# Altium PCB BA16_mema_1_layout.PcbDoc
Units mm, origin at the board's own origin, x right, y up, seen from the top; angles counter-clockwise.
Board outline 42 x 70 mm, 2 copper layers (Top Layer, Bottom Layer); 44 components, 23 nets, 138 pads, 166 vias.
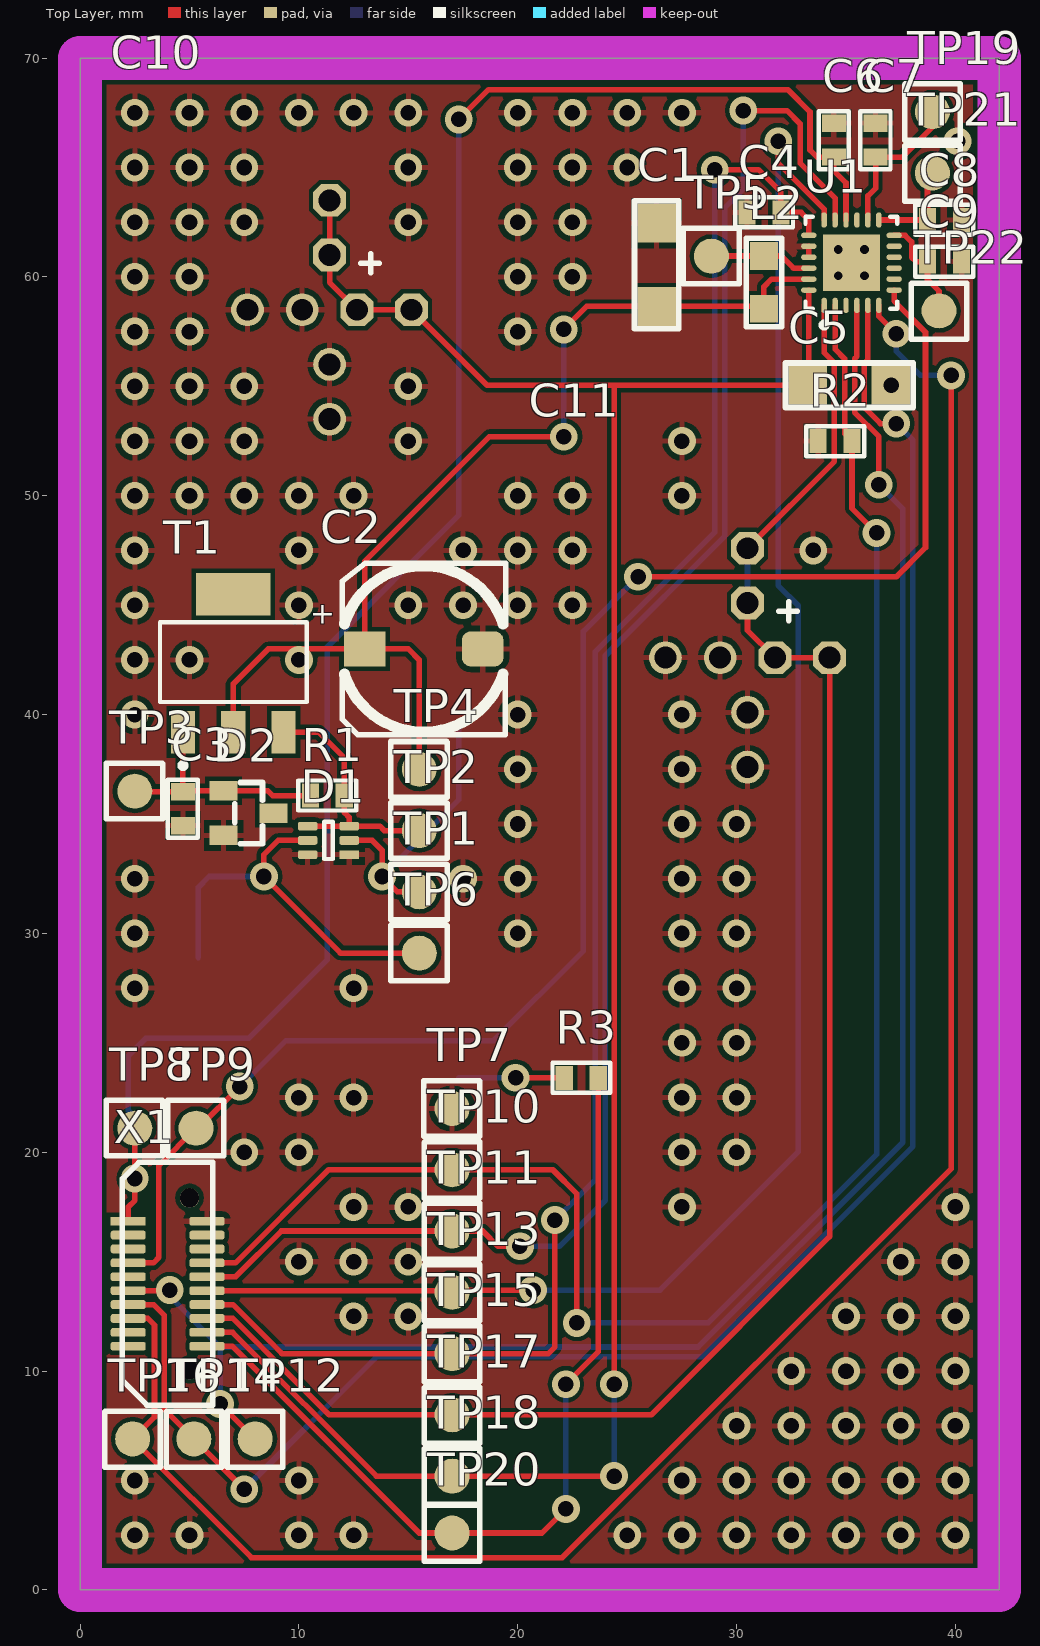
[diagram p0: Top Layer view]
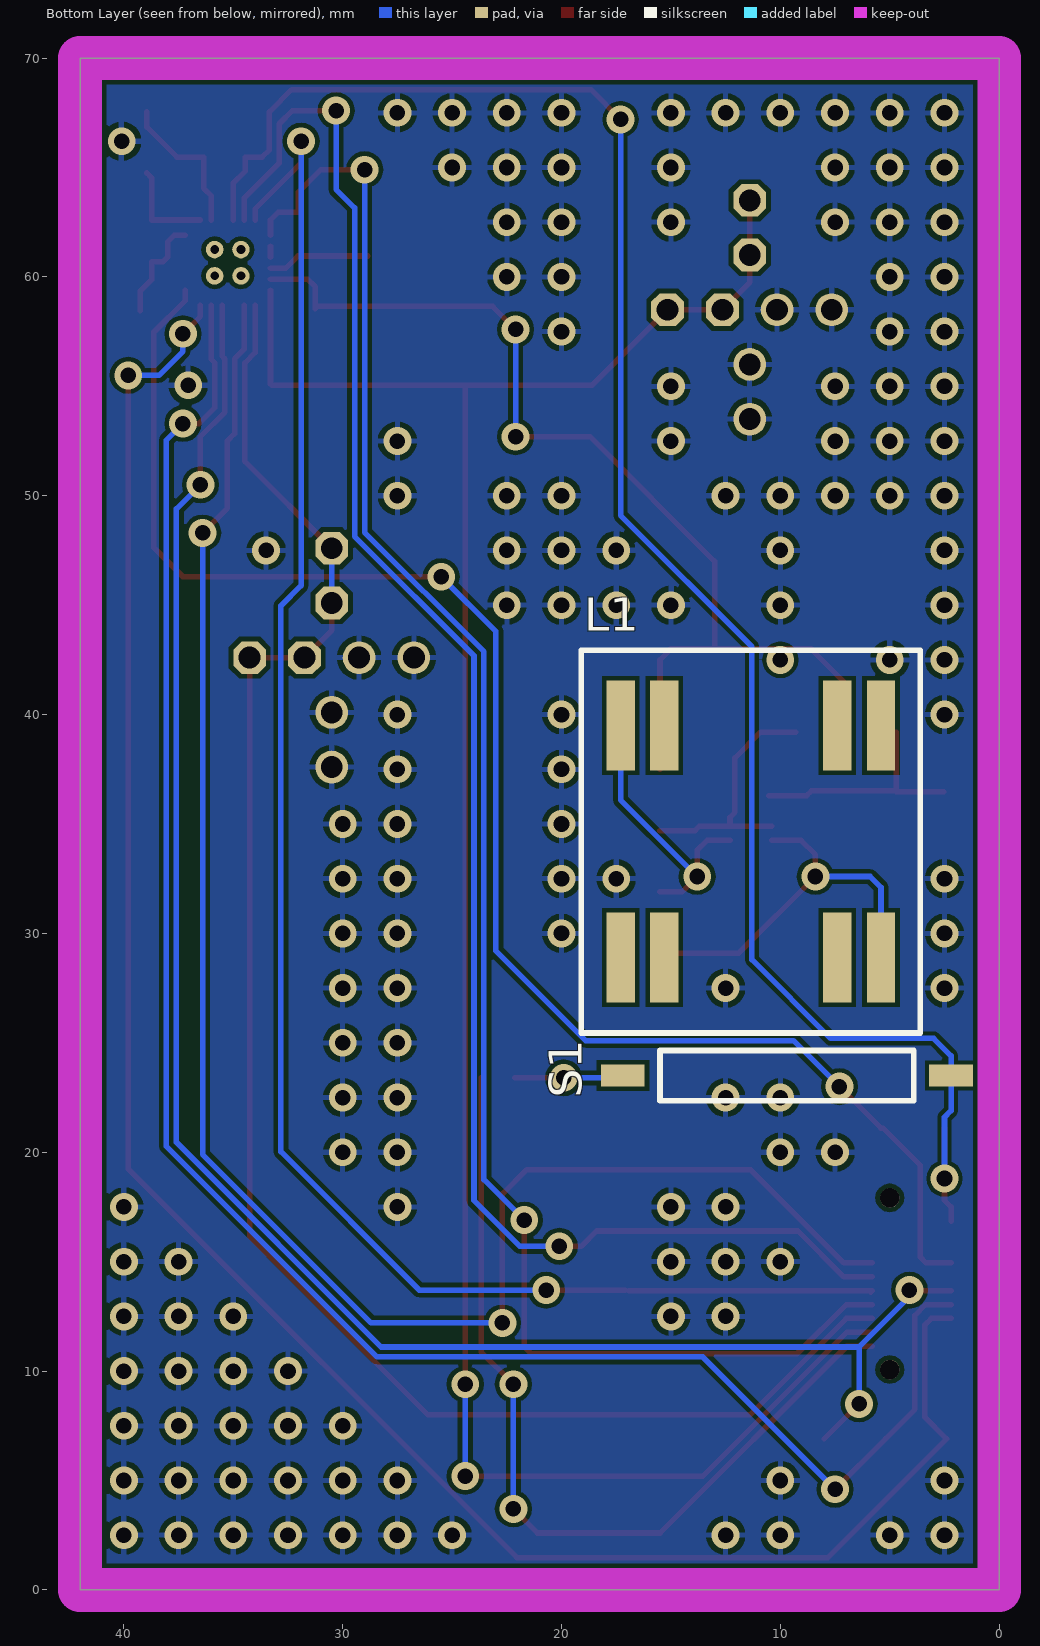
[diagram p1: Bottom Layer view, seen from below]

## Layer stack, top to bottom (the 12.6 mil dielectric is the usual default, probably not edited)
Top Solder: solder mask 0.0102, Solder Resist, Dk 3.5
Top Layer: signal copper 0.0356
Dielectric 1: dielectric 0.32, FR-4, Dk 4.8
Bottom Layer: signal copper 0.0356
Bottom Solder: solder mask 0.0102, Solder Resist, Dk 3.5

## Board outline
0,0 0,70 42,70 42,0

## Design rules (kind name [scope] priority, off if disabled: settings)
Clearance Clearance_EM8500 [All] p1: gap=0.2
Clearance [All] p2: gap=0.254
ComponentClearance ComponentClearance_ELKO_FLEX [HasFootprint('C_RAD_flex')] p1: gap=-5 collisioncheckmode=3 verticalgap=0.254 showdistances=FALSE
ComponentClearance ComponentClearance_TP [HasFootprint('TP SMD')] p2: gap=0 collisioncheckmode=3 verticalgap=0 showdistances=FALSE
ComponentClearance [All] p3: gap=0.254 collisioncheckmode=3 verticalgap=0.254 showdistances=FALSE
PolygonConnect [All] p1: connectstyle=Relief reliefconductorwidth=0.254 reliefentries=4 polygonreliefangle="90 Angle" airgapwidth=0.254
RoutingVias [All] p1: holewidth=0.711 width=1.27 viastyle="Through Hole" minholewidth=0.711 minwidth=1.27 maxholewidth=0.711 maxwidth=1.27
SilkToSilkClearance SilkToSilkClearance_TP [HasFootprint('TP SMD')] p1: silktosilkclearance=0
SilkToSilkClearance [All] p2: silktosilkclearance=0.254
SolderMaskExpansion [All] p1: expansion=0.102
Width [All] p1: maxlimit=0.254 minlimit=0.254 preferedwidth=0.254
28 further rules are at their usual default settings.

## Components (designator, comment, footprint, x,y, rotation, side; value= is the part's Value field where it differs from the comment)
C1 "Cap" "CHIP 1206" 26.35,58.65 r90 top
C2 "47uF 25V" "ELKO SMD-C 6.3x6.3" 15.7,43 r0 top
C3 "1nF" "CHIP 0603" 4.7,35.7 r90 top
C4 "Cap" "CHIP 0603" 31.25,62.95 r180 top
C5 "Cap" "CHIP 1206" 33.25,55.05 r0 top
C6 "Cap" "CHIP 0603" 34.45,66.25 r90 top
C7 "Cap" "CHIP 0603" 36.35,66.25 r90 top
C8 "Cap" "CHIP 0603" 39.5,62.6 r0 top
C9 "Cap" "CHIP 0603" 39.5,60.7 r0 top
C10 "3300uF 25V" C_RAD_FLEX 11.4,58.5 r0 top
C11 "470uF 25V" C_RAD_FLEX 30.5,42.6 r0 top
D1 "HSMS-286P" "SOT-363 (SC-70)" 12.3,33.6 r180 top
D2 "BAS16" SOT-23 7.7,35.5 r270 top
L1 "X-Wicklung" PREMO_3115N_0238J_2 17.3,28.9 r90 bottom
L2 "L" "CHIP 0805" 31.25,59.75 r270 top
R1 "1M" "CHIP 0603" 11.3,36.3 r0 top
R2 "R" "CHIP 0603" 34.5,52.5 r180 top
R3 "10k 0603" "CHIP 0603" 22.9,23.4 r180 top
S1 "Reed Switch" MK16-C-2 9.7,23.5 r180 bottom
T1 "BSP149" SOT-223 4.7,39.2 r0 top
TP1 "TP_SMD" "TP SMD" 15.5,31.9 r0 top
TP2 "TP_SMD" "TP SMD" 15.5,34.7 r0 top
TP3 "TP_SMD" "TP SMD" 2.5,36.5 r0 top
TP4 "TP_SMD" "TP SMD" 15.5,37.5 r0 top
TP5 "TP_SMD" "TP SMD" 28.85,60.95 r0 top
TP6 "TP_SMD" "TP SMD" 15.5,29.1 r0 top
TP7 "TP_SMD" "TP SMD" 17,22 r0 top
TP8 "TP_SMD" "TP SMD" 2.5,21.1 r0 top
TP9 "TP_SMD" "TP SMD" 5.3,21.1 r0 top
TP10 "TP_SMD" "TP SMD" 17,19.2 r90 top
TP11 "TP_SMD" "TP SMD" 17,16.4 r90 top
TP12 "TP_SMD" "TP SMD" 8,6.9 r90 top
TP13 "TP_SMD" "TP SMD" 17,13.6 r90 top
TP14 "TP_SMD" "TP SMD" 5.2,6.9 r90 top
TP15 "TP_SMD" "TP SMD" 17,10.8 r90 top
TP16 "TP_SMD" "TP SMD" 2.4,6.9 r90 top
TP17 "TP_SMD" "TP SMD" 17,8 r90 top
TP18 "TP_SMD" "TP SMD" 17,5.2 r90 top
TP19 "TP_SMD" "TP SMD" 38.95,67.55 r90 top
TP20 "TP_SMD" "TP SMD" 17,2.6 r90 top
TP21 "TP_SMD" "TP SMD" 38.95,64.75 r90 top
TP22 "TP_SMD" "TP SMD" 39.25,58.45 r90 top
U1 "em8500" QFN-24 35.25,60.65 r90 top
X1 "LSS-110-01-F-DV-A-TR" "HEADER SMD 2X10 0.635MM" 2.2,16.85 r0 top locked

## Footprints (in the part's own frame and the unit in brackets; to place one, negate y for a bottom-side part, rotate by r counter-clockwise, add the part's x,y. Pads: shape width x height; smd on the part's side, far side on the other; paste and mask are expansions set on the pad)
C_RAD_FLEX [mm] "KONDENSATOR, AXIAL, Raster 5"
  oct 1.5x1.5 hole 1: 1(0,2.5) 1(0,5) 1(1.25,0) 1(3.75,0)
  round 1.5 hole 1: 2(-3.75,0) 2(-1.25,0) 2(0,-5) 2(0,-2.5)
  silkscreen extent 1.42,1.7 2.27,2.55
"CHIP 0603" [mil] "Chip 0603 Body 1.6x0.8mm"
  rect 31x43 smd: 1(-30.5,0) 2(30.5,0)
  silkscreen extent -52,-27 52,27
"CHIP 0805" [mil] "Chip 0805 Body 2.0x1.2mm"
  rect 50x50 smd: 1(-47.5,0) 2(47.5,0)
  silkscreen extent -80,-32 80,32
"CHIP 1206" [mil] "Chip 1206 Body 3.2x1.6mm"
  rect 70x70 smd: 1(0,0) 2(150,0)
  silkscreen extent -40,-40 190,40
"ELKO SMD-C 6.3x6.3" [mm] "Elko SMD Size C 6.3x6.3mm H = 5.5mm"
  rect 1.9x1.6 smd: 1(-2.7,0)
  rrect50% 1.9x1.6 smd: 2(2.7,0)
  silkscreen extent -3.72,-3.93 3.75,3.93
"HEADER SMD 2X10 0.635MM" [mm] "LSS-110-01-F-DV-A"
  round 0.89 hole 0.89 unplated: 0(2.8,-6.783) 0(2.8,1.068)
  rect 1.6x0.4 smd: 1(0,0)
  rrect50% 1.6x0.4 smd: 2(3.6,0) 3(0,-0.635) 4(3.6,-0.635) 5(0,-1.27) 6(3.6,-1.27) 7(0,-1.905) 8(3.6,-1.905) 9(0,-2.54) 10(3.6,-2.54) 11(0,-3.175) 12(3.6,-3.175) 13(0,-3.81) 14(3.6,-3.81) 15(0,-4.445) 16(3.6,-4.445) 17(0,-5.08) 18(3.6,-5.08) 19(0,-5.715) 20(3.6,-5.715)
  silkscreen extent -0.27,-8.4 3.87,2.69
MK16-C-2 [mm] "REED SENSOR"
  rect 2x1 smd: 1(-7.5,0) 2(7.5,0)
  silkscreen extent -5.8,-1.15 5.8,1.15
PREMO_3115N_0238J_2 [mm] "3D Coil 15x15 2.38mH +/-5% @125kHz"
  rect 4.1x1.3 smd: 1(0,0) 2(0,-2) 3(0,-9.9) 4(0,-11.9) 5(10.6,-11.9) 6(10.6,-9.9) 7(10.6,-2) 8(10.6,0)
  silkscreen extent -3.45,-13.7 14.05,1.8
QFN-24 [mm] "24-Pin Plastic Quad Flat No-Lead 0.5 mm Pitch"
  oval 0.7x0.25 smd: 1(-1.95,1.25) 2(-1.95,0.75) 3(-1.95,0.25) 4(-1.95,-0.25) 5(-1.95,-0.75) 6(-1.95,-1.25) 13(1.95,-1.25) 14(1.95,-0.75) 15(1.95,-0.25) 16(1.95,0.25) 17(1.95,0.75) 18(1.95,1.25)
  oval 0.25x0.7 smd: 7(-1.25,-1.95) 8(-0.75,-1.95) 9(-0.25,-1.95) 10(0.25,-1.95) 11(0.75,-1.95) 12(1.25,-1.95) 19(1.25,1.95) 20(0.75,1.95) 21(0.25,1.95) 22(-0.25,1.95) 23(-0.75,1.95) 24(-1.25,1.95)
  round 0.8 hole 0.4: 25(-0.6,-0.6) 25(-0.6,0.6) 25(0.6,-0.6) 25(0.6,0.6)
  rect 2.6x2.6 smd: 25(0,0)
  silkscreen extent -2.97,-2.1 2.1,2.1, body extent -2.07,-2.07 2.07,2.07, height 1
SOT-23 [mil]
  rect 35x50 smd: 1(-40,-45) 2(40,-45) 3(0,45)
  silkscreen extent -55,-25 55,25
SOT-223 [mm] "SOT-223/SC-73; 4 Leads; Body 6.7 x 7.3 mm, inc. leads (LxW max)"
  rect 1.1x1.95 smd: 1(0,0) 2(2.3,0) 3(4.6,0)
  rect 3.4x1.95 smd: 4(2.3,6.3)
  silkscreen extent -1.05,-1.65 5.65,5.02
"SOT-363 (SC-70)" [mm]
  rect 0.9x0.4 smd: 1(0,0)
  rrect50% 0.9x0.4 smd: 2(0,-0.65) 3(0,-1.3) 4(1.9,-1.3) 5(1.9,-0.65) 6(1.9,0)
  silkscreen extent 0.75,-1.5 1.15,0.2
"TP SMD" [mm] "Testpoint SMD"
  round 1.6 smd: 1(0,0)
  silkscreen extent -1.3,-1.27 1.27,1.27

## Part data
C1 C4 C5 C6 C7 C8 C9: library part C, "Capacitor"
C2 C10 C11: library part "C POL", "Capasitor Polarisiert"
C3: library part "C 50V", "Capacitor 50V"
D1: "Diode Schottky Quadro"
D2: library part D, "Diode"
L1: library part "PREMO 3015 0238J 2", "Inductor"
L2: "Ind"
R1 R3: library part R, "Resistor"
R2: "Resistor"
S1: library part "SWITCH MICRO NO", "Switch Micro Normal Open"
T1: "MOSFET N-Kanal"
TP1 TP2 TP3 TP4 TP5 TP6 TP7 TP8 TP9 TP10 TP11 TP12 TP13 TP14 TP15 TP16 TP17 TP18 TP19 TP20 TP21 TP22: "Testpoint SMD"
X1: library part "HDR 20 POL ABW", "Header 100 mil 20 Pol"

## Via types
v1: diameter 1.27, hole 0.711, Top Layer to Bottom Layer, 166 vias

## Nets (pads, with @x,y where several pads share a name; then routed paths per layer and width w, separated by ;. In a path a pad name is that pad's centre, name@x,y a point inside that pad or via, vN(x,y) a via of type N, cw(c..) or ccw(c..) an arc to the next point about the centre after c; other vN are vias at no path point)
BAT_LOW: TP13.1 U1.18 X1.12 | length 80.6
  Top Layer w0.254: X1.12@5.875,13.6 X1.12 TP13.1@16.925,13.675 ; TP13.1@17.1,13.7 v1(20.7,13.7) ; v1(31.9,66.2) 31.9,65.2 34,63.1 U1.18
  Bottom Layer w0.254: v1(20.7,13.7) 26.5,13.7 32.827,20.027 32.827,44.973 31.9,45.9 v1(31.9,66.2)
EM_CS: TP9.1 U1.7 X1.7 | length 73.2
  Top Layer w0.254: X1.7 3.345,14.945 3.6,15.2 3.6,19.4 TP9.1 ; TP9.1@5.4,21.1 v1(7.3,23) ; v1(25.5,46.3) 37.3,46.3 38.633,47.633 38.633,57.473 37.2,58.906 U1.7
  Bottom Layer w0.254: v1(7.3,23) 9.4,25.1 18.9,25.1 23,29.2 23,43.8 v1(25.5,46.3)
GND: C1.2 C2.2 C3.1 C4.2 C5.2 C6.2 C7.2 C8.2 C9.2 C10.2 C11.2 D1.1 D1.6 D2.2 R2.2 TP7.1 U1.20 U1.21 X1.2 | length 0.5
  Top Layer w0.254: U1.21 U1.20
  other v1: 2.5,2.5 5,2.5 10,2.5 12.5,2.5 25,2.5 27.5,2.5 30,2.5 32.5,2.5 35,2.5 37.5,2.5 40,2.5 2.5,5 10,5 27.5,5 30,5 32.5,5 35,5 37.5,5 40,5 30,7.5 32.5,7.5 35,7.5 35,7.5 37.5,7.5 40,7.5 32.5,10 35,10 37.5,10 40,10 12.5,12.5 15,12.5 35,12.5 37.5,12.5 40,12.5 10,15 12.5,15 15,15 37.5,15 40,15 12.5,17.5 15,17.5 27.5,17.5 40,17.5 7.5,20 10,20 27.5,20 30,20 10,22.5 12.5,22.5 27.5,22.5 30,22.5 27.5,25 30,25 2.5,27.5 12.5,27.5 27.5,27.5 30,27.5 2.5,30 20,30 27.5,30 30,30 2.5,32.5 17.5,32.5 20,32.5 27.5,32.5 30,32.5 20,35 27.5,35 30,35 20,37.5 27.5,37.5 2.5,40 20,40 27.5,40 2.5,42.5 5,42.5 2.5,45 10,45 15,45 17.5,45 20,45 22.5,45 2.5,47.5 10,47.5 17.5,47.5 20,47.5 22.5,47.5 33.5,47.5 2.5,50 5,50 7.5,50 10,50 12.5,50 20,50 22.5,50 27.5,50 2.5,52.5 5,52.5 7.5,52.5 15,52.5 27.5,52.5 2.5,55 5,55 7.5,55 15,55 37.06,55.05 2.5,57.5 5,57.5 20,57.5 2.5,60 5,60 20,60 22.5,60 2.5,62.5 5,62.5 7.5,62.5 15,62.5 20,62.5 22.5,62.5 2.5,65 5,65 7.5,65 15,65 20,65 22.5,65 25,65 40.1,66.2 2.5,67.5 5,67.5 7.5,67.5 10,67.5 12.5,67.5 15,67.5 20,67.5 22.5,67.5 25,67.5 27.5,67.5
HRV_LOW: TP11.1 U1.17 X1.10 | length 80.5
  Top Layer w0.254: X1.10 7.11,14.31 9.2,16.4 TP11.1 18.4,16.4 19.1,15.7 v1(20.1,15.7) ; v1(30.3,67.6) 32.3,67.6 32.9,67 32.9,65.2 34.5,63.6 U1.17
  Bottom Layer w0.254: v1(20.1,15.7) 21.9,15.7 24,17.8 24,42.687 29.454,48.141 29.454,63.154 30.3,64 v1(30.3,67.6)
MCU_MISO: TP14.1 U1.5 X1.13 | length 88.2
  Top Layer w0.254: X1.13 3.36,13.04 3.854,12.546 3.854,8.246 TP14.1 v1(7.5,4.6) ; U1.5 36,56.23 35.844,56.074 35.844,54.026 36.57,53.3 v1(37.3,53.3)
  Bottom Layer w0.254: v1(7.5,4.6) 13.546,10.646 28.43,10.646 38.054,20.27 38.054,52.546 v1(37.3,53.3)
MCU_MOSI: TP12.1 U1.4 X1.11 | length 87.2
  Top Layer w0.254: X1.11 4.075,13.675 v1(4.1,13.7) ; v1(6.4,8.5) TP12.1 ; U1.4 35.5,56.372 35.39,56.262 35.39,53.81 36.5,52.7 v1(36.5,50.5)
  Bottom Layer w0.254: v1(4.1,13.7) 4.1,13.4 6.4,11.1 ; v1(36.5,50.5) 37.6,49.4 37.6,20.458 28.242,11.1 6.4,11.1 ; 6.4,11.1 v1(6.4,8.5) 6.4,11.1
MCU_SCLK: TP16.1 U1.6 X1.15 | length 95.6
  Top Layer w0.254: X1.15 3.095,12.405 3.4,12.1 3.4,7.9 TP16.1 7.827,1.473 22.033,1.473 39.8,19.24 v1(39.8,55.5) ; U1.6 36.5,58.2 v1(37.3,57.4)
  Bottom Layer w0.254: v1(37.3,57.4) 37.3,56.6 38.4,55.5 v1(39.8,55.5)
NetC3_2: C3.2 D2.1 R1.1 T1.1 TP3.1 | length 10.8
  Top Layer w0.254: TP3.1@2.525,36.475 C3.2 T1.1 ; C3.2@4.741,36.516 D2.1 8.584,36.516 8.8,36.3 R1.1
NetD1_2: D1.2 L1.8 TP1.1 | length 13.2
  Top Layer w0.254: D1.2 13.35,34.25 13.8,33.8 v1(13.8,32.6) 14.5,31.9 TP1.1
  Bottom Layer w0.254: v1(13.8,32.6) 17.3,36.1 L1.8
NetD1_3: D1.3 D1.4 R1.2 T1.3 TP2.1 | length 11.7
  Top Layer w0.254: T1.3 10.9,39.2 12.075,38.025 R1.2 12.075,35.525 12.3,35.3 D1.3 ; D1.4 D1.3 ; TP2.1 13.9,34.7 13.7,34.9 D1.3
NetD1_5: D1.5 L1.4 TP6.1 | length 18.2
  Top Layer w0.254: D1.5 9.05,34.25 8.4,33.6 v1(8.4,32.6) 11.9,29.1 TP6.1
  Bottom Layer w0.254: L1.4 5.4,32.1 5.9,32.6 v1(8.4,32.6)
NetL2_1: L2.1 TP5.1 U1.22 | length 4.7
  Top Layer w0.254: TP5.1@28.857,60.956 L2.1 32.044,60.956 32.6,60.4 U1.22
NetR3_2: R3.2 S1.1 | length 4.8
  Top Layer w0.254: v1(19.9,23.4) R3.2
  Bottom Layer w0.254: S1.1@17.3,23.4 v1(19.9,23.4)
REED_SWITCH: R3.1 TP20.1 X1.20 | length 40.7
  Top Layer w0.254: X1.20 6.965,11.135 15.5,2.6 21.1,2.6 v1(22.2,3.7) ; v1(22.2,9.4) 23.675,10.875 R3.1
  Bottom Layer w0.254: v1(22.2,3.7) v1(22.2,9.4)
VAUX_VCC0: C9.1 TP22.1 U1.12 | length 4.9
  Top Layer w0.254: U1.12 37.7,61.9 38,61.6 38,60.9 38.2,60.7 C9.1 38.725,59.875 39.25,59.35 TP22.1
VAUX_VCC1: C8.1 TP21.1 U1.13 | length 4.5
  Top Layer w0.254: U1.13 C8.1 38.725,64.525 TP21.1
VAUX_VCC2: C7.1 TP19.1 U1.14 | length 6.9
  Top Layer w0.254: U1.14 36,63.7 36.35,64.05 C7.1 37.575,65.475 38.95,66.85 TP19.1
VCC: C1.1 C2.1 L2.2 T1.2 TP4.1 U1.23 | length 49.6
  Top Layer w0.254: T1.2 7,41.4 8.6,43 C2.1 ; TP4.1 15.5,42.5 15,43 C2.1 ; v1(22.1,52.7) 18.7,52.7 13,47 C2.1 ; v1(22.1,57.6) 23.15,58.65 C1.1 L2.2@31.144,58.65 ; L2.2 31.25,59.55 31.6,59.9 U1.23
  Bottom Layer w0.254: v1(22.1,52.7) v1(22.1,57.6)
  other v1: 10,42.5
VCC_LTS: C5.1 C10.1 TP18.1 U1.24 X1.18 | length 103
  Top Layer w0.254: X1.18 6.972,11.77 13.542,5.2 TP18.1 v1(24.4,5.2) ; C10.1@11.4,63.5 11.4,61 11.4,59.75 12.65,58.5 15.15,58.5 18.6,55.05 24.4,55.05 ; v1(24.4,9.4) 24.4,55.05 ; C5.1 24.4,55.05 ; C5.1@33.3,55.1 U1.24
  Bottom Layer w0.254: v1(24.4,5.2) v1(24.4,9.4)
VCC_STS: C11.1 TP17.1 U1.1 X1.16 | length 81.1
  Top Layer w0.254: X1.16 6.979,12.405 11.384,8 TP17.1 26.1,8 34.25,16.15 34.25,42.6 31.75,42.6 30.5,43.85 C11.1@30.5,45.1 ; C11.1@30.5,47.6 34.466,51.566 34.466,56.074 34,56.54 U1.1
  Bottom Layer w0.254: C11.1@30.5,45.1 C11.1@30.5,47.6
VREG: C4.1 TP15.1 U1.19 X1.14 | length 80.3
  Top Layer w0.254: X1.14 6.986,13.04 9.226,10.8 TP15.1 21.4,10.8 21.7,11.1 v1(21.7,16.9) ; v1(29,64.9) 31,64.9 32.025,63.875 C4.1 32.95,62.95 33.3,62.6 U1.19
  Bottom Layer w0.254: v1(21.7,16.9) 23.546,18.746 23.546,42.875 29,48.329 v1(29,64.9)
VSUP: C6.1 S1.2 TP8.1 U1.16 X1.1 | length 85
  Top Layer w0.254: X1.1 2.2,17.5 2.5,17.8 v1(2.5,18.8) TP8.1 ; v1(17.3,67.2) 18.662,68.562 32.338,68.562 33.354,67.546 33.354,65.8 33.679,65.475 C6.1 34.45,64.85 35,64.3 U1.16
  Bottom Layer w0.254: v1(2.5,18.8) 2.5,21.6 2.2,21.9 S1.2 2.2,24.4 3,25.2 7.7,25.2 11.3,28.8 11.3,43.1 17.3,49.1 v1(17.3,67.2)
WAKE_UP: R2.1 TP10.1 U1.2 X1.8 | length 81.5
  Top Layer w0.254: X1.8 7.103,14.945 11.358,19.2 TP10.1 21.6,19.2 22.7,18.1 v1(22.7,12.2) ; U1.2 34.5,56.698 34.936,56.262 34.936,52.839 R2.1 35.275,49.425 v1(36.4,48.3)
  Bottom Layer w0.254: v1(22.7,12.2) 28.7,12.2 36.4,19.9 v1(36.4,48.3)
pads on no net: D2.3 L1.1 L1.2 L1.3 L1.5 L1.6 L1.7 T1.4 U1.3 U1.8 U1.9 U1.10 U1.11 U1.15 U1.25 X1.0 X1.3 X1.4 X1.5 X1.6 X1.9 X1.17 X1.19

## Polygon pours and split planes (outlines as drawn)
GND on Top Layer "Top Layer-GND" (solid, remove dead copper, pour order 2): 0,70 0,0 42,0 42,70
GND on Bottom Layer "Bottom Layer-GND" (solid, remove dead copper, pour order 4): 0,70 0,0 42,0 42,70

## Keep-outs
Top Layer:
  the board outline again, w2
Bottom Layer:
  the board outline again, w2

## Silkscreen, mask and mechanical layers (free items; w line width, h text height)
Mechanical 1:
  lines w0.254: 0,8.45 42,8.45 ; 0,19.55 42,19.55 ; 0,32 42,32 ; 1.91,0 1.91,70 ; 0,0 0,70 42,70 42,0 0,0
